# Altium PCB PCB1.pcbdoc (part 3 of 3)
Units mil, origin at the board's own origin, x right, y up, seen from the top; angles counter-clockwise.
Board outline 5971.11 x 4241.46 mil, 4 copper layers (Top Layer, Inner1, Inner2, Bottom Layer); 197 components, 112 nets, 603 pads, 396 vias.
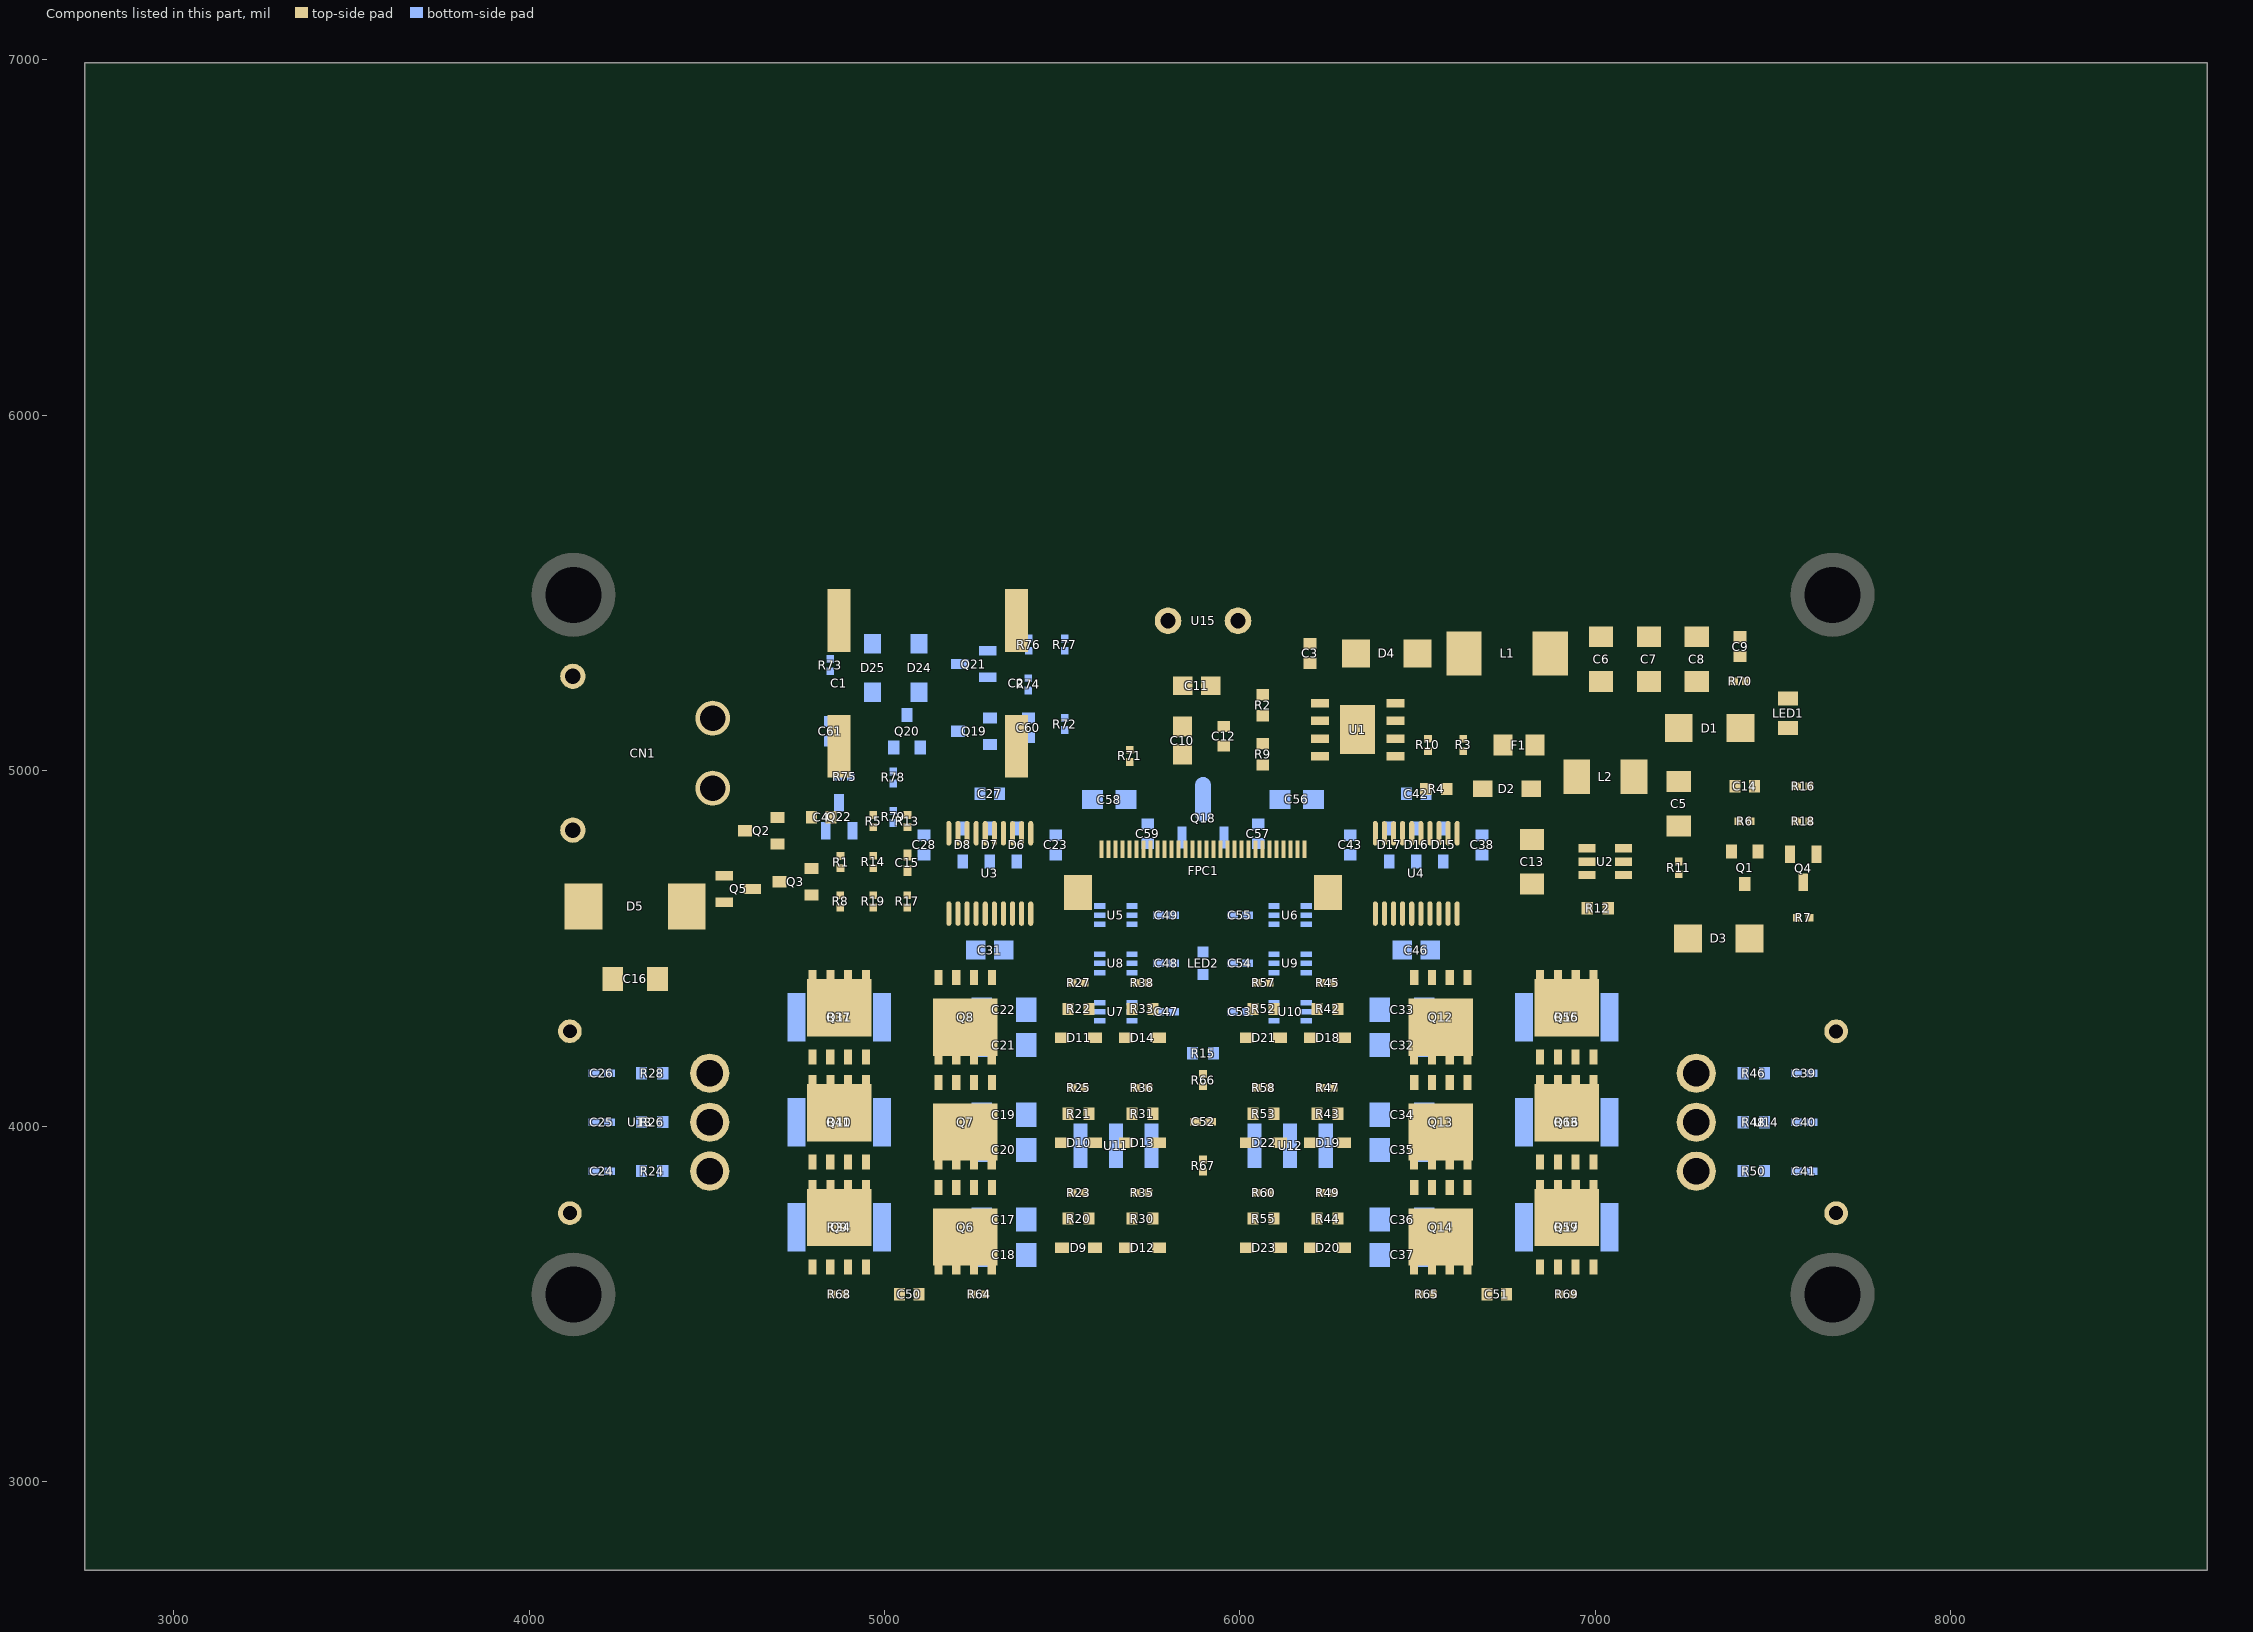
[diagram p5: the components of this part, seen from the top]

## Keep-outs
Top Layer:
  region: 6599.01,5476.96 6902.01,5476.96 6902.01,5183.96 6599.01,5183.96
  region: 6909.01,5095.96 7148.01,5095.96 7148.01,4868.67 6909.01,4868.67
Inner1:
  region: 6599.01,5476.96 6903.01,5476.96 6903.01,5183.96 6599.01,5183.96
  region: 6909.01,5095.96 7148.01,5095.96 7148.01,4868.67 6909.01,4868.67
Board Outline Layer:
  lines w10: 3999.32,3792.29 ccw(c4033.61,3759.91) 3986.54,3762.68 3986.54,3526.46 ccw(c4124.33,3526.46) 4124.33,3388.67 4360.55,3388.67 ccw(c4357.78,3435.74) 4390.16,3401.45 4426.35,3437.65 cw(c4458.73,3403.37) 4455.97,3450.44 7336,3450.44 cw(c7333.23,3403.37) 7365.61,3437.66 7401.8,3401.46 ccw(c7434.18,3435.74) 7431.42,3388.67 7667.64,3388.67 ccw(c7667.64,3526.46) 7805.43,3526.46 7805.43,3762.68 ccw(c7758.35,3759.91) 7792.64,3792.29 7756.45,3828.48 cw(c7790.73,3860.86) 7743.65,3858.1 7743.65,5163.33 cw(c7790.73,5160.56) 7756.44,5192.93 7792.64,5229.13 ccw(c7758.35,5261.51) 7805.43,5258.74 7805.43,5494.96 ccw(c7667.64,5494.96) 7667.64,5632.76 7431.42,5632.76 ccw(c7434.18,5585.68) 7401.81,5619.97 7365.61,5583.77 cw(c7333.23,5618.06) 7336,5570.98 4455.98,5570.98 ; 3999.32,5229.14 cw(c4033.61,5261.51) 3986.54,5258.74 3986.54,5494.96 cw(c4124.33,5494.96) 4124.33,5632.76 4360.55,5632.76 cw(c4357.78,5585.68) 4390.16,5619.97 4426.35,5583.77 ccw(c4458.73,5618.06) 4455.96,5570.98 ; 3999.33,3792.29 4035.52,3828.48 ; 3999.33,5229.13 4035.52,5192.94 ; 4035.53,3828.49 ccw(c4001.24,3860.86) 4048.31,3858.1 4048.31,5163.33 ccw(c4001.24,5160.56) 4035.53,5192.93

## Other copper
Top Layer:
  drawing of 460 lines, arcs and shapes, not listed
Inner1:
  region net M0_ISENSOR_PA: 4884.51,3607.82 4884.51,3599.82 4882.91,3599.6 4881.23,3599 4879.64,3598.16 4878.32,3597.19 4878.32,3610.46 4879.64,3609.49 4881.23,3608.65 4882.91,3608.05
  region net M1_ISENSOR_PC: 6857.46,3599.8 6857.46,3607.8 6859.06,3608.02 6860.74,3608.62 6862.34,3609.47 6863.65,3610.43 6863.65,3597.16 6862.34,3598.13 6860.74,3598.97 6859.06,3599.57
  region net $1N11350: 5163.83,4381.48 5163.83,4373.48 5162.23,4373.26 5160.55,4372.66 5158.96,4371.81 5157.64,4370.84 5157.64,4384.12 5158.96,4383.15 5160.55,4382.31 5162.23,4381.71
  region net $1N11350: 5503.37,4373.48 5504.15,4381.48 5505.74,4381.69 5507.41,4382.25 5509,4383.03 5510.35,4383.93 5509.57,4370.68 5508.28,4371.71 5506.69,4372.61 5504.98,4373.24
  region net M0_V: 5477.18,4113.35 5482.84,4119.01 5484.13,4118.04 5485.74,4117.27 5487.47,4116.74 5489.08,4116.49 5479.7,4107.11 5479.45,4108.72 5478.92,4110.45 5478.15,4112.06
  region net M0_U: 5477.18,3818.15 5482.84,3823.81 5484.13,3822.84 5485.74,3822.07 5487.47,3821.54 5489.08,3821.29 5479.7,3811.91 5479.45,3813.52 5478.92,3815.25 5478.15,3816.86
  region net $1N10733: 5163.83,4086.18 5163.83,4078.18 5162.23,4077.95 5160.55,4077.36 5158.96,4076.51 5157.64,4075.54 5157.64,4088.82 5158.96,4087.85 5160.55,4087.01 5162.23,4086.41
  region net $1N8638: 5163.83,3790.98 5163.83,3782.98 5162.23,3782.76 5160.55,3782.16 5158.96,3781.31 5157.64,3780.34 5157.64,3793.62 5158.96,3792.65 5160.55,3791.81 5162.23,3791.21
  region net $1N8638: 5597.11,3801.11 5591.45,3806.77 5592.42,3808.06 5593.19,3809.68 5593.72,3811.4 5593.97,3813.02 5603.35,3803.63 5601.74,3803.38 5600.01,3802.85 5598.4,3802.08
  region net M0_ISENSOR_PC: 5599.99,4391.61 5594.33,4397.27 5595.31,4398.56 5596.07,4400.18 5596.6,4401.9 5596.85,4403.52 5606.24,4394.13 5604.62,4393.88 5602.9,4393.35 5601.28,4392.58
  region net $1N11388: 5800.4,4390.91 5792.4,4390.91 5792.17,4392.51 5791.58,4394.2 5790.73,4395.79 5789.76,4397.11 5803.04,4397.11 5802.07,4395.79 5801.22,4394.2 5800.63,4392.51
  region net M0_ISENSOR_NA: 5658.79,4096.31 5653.13,4101.97 5654.1,4103.26 5654.87,4104.88 5655.4,4106.6 5655.65,4108.22 5665.04,4098.83 5663.42,4098.58 5661.7,4098.05 5660.08,4097.28
  region net $1N10771: 5787.11,4096.31 5781.45,4101.97 5782.42,4103.26 5783.19,4104.88 5783.72,4106.6 5783.97,4108.22 5793.35,4098.83 5791.74,4098.58 5790.01,4098.05 5788.4,4097.28
  region net $1N11388: 5119.33,4171.71 5119.33,4163.71 5117.73,4163.49 5116.05,4162.89 5114.46,4162.04 5113.14,4161.08 5113.14,4174.35 5114.46,4173.38 5116.05,4172.54 5117.73,4171.94
  region net $1N10771: 5119.33,3876.46 5119.33,3868.46 5117.73,3868.23 5116.05,3867.63 5114.46,3866.79 5113.14,3865.82 5113.14,3879.1 5114.46,3878.13 5116.05,3877.28 5117.73,3876.68
  region net M1_ISENSOR_NA: 6138.83,4101.97 6133.17,4096.31 6131.88,4097.28 6130.27,4098.05 6128.54,4098.58 6126.93,4098.83 6136.31,4108.22 6136.56,4106.6 6137.09,4104.88 6137.86,4103.26
  region net $1N20194: 6478.35,4373.46 6478.32,4381.46 6479.92,4381.69 6481.61,4382.29 6483.2,4383.14 6484.52,4384.11 6484.54,4370.83 6483.22,4371.8 6481.63,4372.64 6479.95,4373.24
  region net $1N20187: 6478.34,4078.16 6478.33,4086.16 6479.93,4086.39 6481.62,4086.99 6483.21,4087.83 6484.53,4088.8 6484.53,4075.53 6483.21,4076.49 6481.62,4077.34 6479.94,4077.94
  region net $1N20219: 6466.21,3782.98 6466.21,3790.98 6467.81,3791.21 6469.5,3791.81 6471.09,3792.65 6472.41,3793.62 6472.41,3780.34 6471.09,3781.31 6469.5,3782.16 6467.81,3782.76
  region net $1N20159: 6672.63,3859.64 6672.63,3867.64 6674.23,3867.87 6675.92,3868.46 6677.51,3869.31 6678.83,3870.28 6678.83,3857 6677.51,3857.97 6675.92,3858.81 6674.23,3859.41
  region net M1_ISENSOR_PC: 6094.66,3872.78 6089.18,3866.94 6087.89,3867.91 6086.26,3868.68 6084.52,3869.19 6082.9,3869.42 6092.1,3878.99 6092.37,3877.38 6092.91,3875.67 6093.69,3874.07
  region net $1N20164: 6060.58,4362.17 6054.92,4356.51 6053.63,4357.48 6052.02,4358.25 6050.3,4358.78 6048.68,4359.03 6058.07,4368.42 6058.31,4366.8 6058.84,4365.08 6059.61,4363.46
  region net M1_U: 6320.17,4406.96 6320.17,4398.96 6318.57,4398.74 6316.89,4398.14 6315.3,4397.29 6313.98,4396.33 6313.98,4409.6 6315.3,4408.63 6316.89,4407.79 6318.57,4407.19
  region net $1N20194: 6305.9,4381.46 6305.9,4373.46 6304.3,4373.24 6302.62,4372.64 6301.02,4371.79 6299.71,4370.83 6299.71,4384.1 6301.02,4383.13 6302.62,4382.29 6304.3,4381.69
  region net M1_W: 6308.81,3823.81 6314.47,3818.15 6313.5,3816.86 6312.73,3815.25 6312.2,3813.52 6311.96,3811.91 6302.57,3821.29 6304.19,3821.54 6305.91,3822.07 6307.52,3822.84
  region net M1_V: 6309.11,4119.01 6314.77,4113.35 6313.8,4112.06 6313.03,4110.45 6312.5,4108.72 6312.25,4107.11 6302.86,4116.49 6304.48,4116.74 6306.2,4117.27 6307.82,4118.04
  region net M1_LC: 6124.69,3745.18 6130.35,3750.84 6131.64,3749.87 6133.25,3749.1 6134.98,3748.57 6136.59,3748.32 6127.21,3738.94 6126.96,3740.55 6126.43,3742.28 6125.66,3743.89
  region net M1_LB: 6124.69,4040.38 6130.35,4046.04 6131.64,4045.07 6133.25,4044.3 6134.98,4043.77 6136.59,4043.52 6127.21,4034.14 6126.96,4035.75 6126.43,4037.48 6125.66,4039.09
  region net M1_LC: 6346.63,4569.85 6352.29,4575.51 6353.58,4574.54 6355.2,4573.77 6356.92,4573.24 6358.54,4573 6349.15,4563.61 6348.9,4565.23 6348.37,4566.95 6347.6,4568.56
  region net M1_LB: 6333.63,4547.65 6339.29,4553.31 6340.58,4552.34 6342.2,4551.57 6343.92,4551.04 6345.54,4550.8 6336.15,4541.41 6335.9,4543.03 6335.37,4544.75 6334.6,4546.36
  region net M1_W: 6596.93,4701.67 6591.27,4696.01 6589.98,4696.98 6588.37,4697.75 6586.64,4698.28 6585.03,4698.53 6594.41,4707.92 6594.66,4706.3 6595.19,4704.58 6595.96,4702.96
  region net M1_U: 6444.08,4711.36 6444.08,4703.36 6442.48,4703.14 6440.8,4702.54 6439.2,4701.69 6437.88,4700.73 6437.88,4714 6439.2,4713.03 6440.8,4712.19 6442.48,4711.59
  region net M0_U: 5236.03,4695.31 5228.03,4695.31 5227.8,4696.91 5227.21,4698.6 5226.36,4700.19 5225.39,4701.51 5238.67,4701.51 5237.7,4700.19 5236.86,4698.6 5236.26,4696.91
  region net M0_W: 5389.58,4695.31 5381.58,4695.31 5381.35,4696.91 5380.76,4698.6 5379.91,4700.19 5378.94,4701.51 5392.22,4701.51 5391.25,4700.19 5390.41,4698.6 5389.81,4696.91
  region net $1N20164: 6552.79,4154.91 6552.79,4162.91 6554.39,4163.14 6556.08,4163.74 6557.67,4164.58 6558.99,4165.55 6558.99,4152.28 6557.67,4153.25 6556.08,4154.09 6554.39,4154.69
  region net M1_ISENSOR_PA: 6672.65,4190.35 6672.65,4198.35 6674.25,4198.57 6675.93,4199.17 6677.52,4200.02 6678.84,4200.99 6678.84,4187.71 6677.52,4188.68 6675.93,4189.52 6674.25,4190.12
  region net M1_ISENSOR_NA: 6672.63,3895.07 6672.63,3903.07 6674.23,3903.3 6675.92,3903.9 6677.51,3904.74 6678.83,3905.71 6678.83,3892.43 6677.51,3893.4 6675.92,3894.25 6674.23,3894.85
  region net M0_ISENSOR_PC: 5119.33,4198.32 5119.33,4190.32 5117.73,4190.1 5116.05,4189.5 5114.46,4188.65 5113.14,4187.69 5113.14,4200.96 5114.46,4199.99 5116.05,4199.15 5117.73,4198.55
  region net M0_ISENSOR_NA: 5119.33,3903.07 5119.33,3895.07 5117.73,3894.84 5116.05,3894.24 5114.46,3893.4 5113.14,3892.43 5113.14,3905.71 5114.46,3904.74 5116.05,3903.89 5117.73,3903.3
  region net M0_BK_OUT: 5446.98,5360.18 5438.98,5360.18 5438.76,5361.78 5438.16,5363.47 5437.31,5365.06 5436.35,5366.38 5449.62,5366.38 5448.65,5365.06 5447.81,5363.47 5447.21,5361.78
  region net M1_BK_OUT: 5481.03,5001.96 5481.03,4993.96 5479.43,4993.74 5477.75,4993.14 5476.16,4992.29 5474.84,4991.33 5474.84,5004.6 5476.16,5003.63 5477.75,5002.79 5479.43,5002.19
  region net M0_V: 5312.81,4864.61 5304.81,4864.61 5304.58,4866.21 5303.99,4867.9 5303.14,4869.49 5302.17,4870.81 5315.45,4870.81 5314.48,4869.49 5313.64,4867.9 5313.04,4866.21
  region net M1_V: 6512.81,4865.76 6504.81,4865.75 6504.58,4867.35 6503.99,4869.04 6503.14,4870.63 6502.17,4871.95 6515.45,4871.95 6514.48,4870.63 6513.63,4869.04 6513.04,4867.36
  region net M0_ADC_A: 5849.93,4725.31 5841.93,4726.57 5841.74,4728.15 5841.21,4729.81 5840.46,4731.4 5839.61,4732.77 5852.83,4731.51 5851.76,4730.24 5850.84,4728.64 5850.18,4726.92
  region net M1_TIM8_CH3N: 6461.62,4633.43 6453.62,4633.43 6453.39,4634.91 6452.79,4636.35 6451.95,4637.69 6450.98,4638.89 6464.25,4638.89 6463.29,4637.69 6462.44,4636.35 6461.84,4634.91
  region net M1_TIM8_CH1: 6419.98,4640.74 6419.98,4648.74 6421.58,4648.97 6423.26,4649.57 6424.85,4650.41 6426.17,4651.38 6426.17,4638.11 6424.85,4639.07 6423.26,4639.92 6421.58,4640.52
  region net M1_TIM8_CH3N: 6136.35,4845.77 6130.7,4851.43 6131.67,4852.72 6132.44,4854.33 6132.96,4856.05 6133.21,4857.67 6142.6,4848.28 6140.98,4848.04 6139.26,4847.51 6137.64,4846.74
  region net M1_TIM8_CH1: 6153.39,4811.14 6147.74,4805.48 6146.45,4806.45 6144.83,4807.22 6143.11,4807.75 6141.49,4808 6150.88,4817.38 6151.12,4815.77 6151.65,4814.04 6152.42,4812.43
  region net M0_ADC_A: 5639.67,4630.69 5645.33,4625.03 5644.36,4623.74 5643.59,4622.13 5643.06,4620.41 5642.82,4618.79 5633.43,4628.18 5635.05,4628.42 5636.77,4628.95 5638.38,4629.72
  region net M0_ADC_C: 5627.68,4528.37 5635.68,4528.37 5635.91,4526.77 5636.51,4525.09 5637.35,4523.5 5638.32,4522.18 5625.05,4522.18 5626.01,4523.5 5626.86,4525.09 5627.46,4526.77
  region net M0_ADC: 5988.56,4706.91 5980.56,4706.91 5980.34,4708.51 5979.74,4710.2 5978.9,4711.79 5977.93,4713.11 5991.2,4713.11 5990.23,4711.79 5989.39,4710.2 5988.79,4708.51
  region net VOLTAGE_ADC: 5874.8,4743.65 5880.45,4749.31 5881.74,4748.34 5883.36,4747.57 5885.08,4747.04 5886.7,4746.8 5877.31,4737.41 5877.06,4739.03 5876.54,4740.75 5875.77,4742.36
  region net M0_ADC: 5645.58,4373.86 5645.58,4365.86 5643.98,4365.64 5642.29,4365.04 5640.7,4364.19 5639.38,4363.23 5639.38,4376.5 5640.7,4375.53 5642.29,4374.69 5643.98,4374.09
  region net M1_ISENSOR_PA: 6257.98,4420.75 6249.98,4420.75 6249.76,4422.35 6249.16,4424.04 6248.31,4425.63 6247.35,4426.95 6260.62,4426.95 6259.65,4425.63 6258.81,4424.04 6258.21,4422.35
  region net +5V: 7417.78,5048.56 7397.78,5048.56 7397.7,5051.21 7397.47,5053.71 7396.78,5058.09 7396.1,5061.3 7395.78,5062.96 7419.78,5062.96 7419.47,5061.3 7418.78,5058.09 7418.1,5053.71 7417.87,5051.21
  region net M1_BK_OUT: 5696.93,4818.63 5696.93,4826.63 5698.52,4826.86 5700.21,4827.45 5701.8,4828.3 5703.12,4829.27 5703.12,4815.99 5701.8,4816.96 5700.21,4817.81 5698.52,4818.4
  region net M0_BK_OUT: 5686.73,4870.22 5694.73,4868.05 5694.91,4866.49 5695.37,4864.84 5696.03,4863.24 5696.79,4861.85 5683.69,4864.02 5684.81,4865.24 5685.78,4866.85 5686.47,4868.6
  region net M0_BK_OUT: 5677.93,4862.85 5683.59,4868.51 5684.88,4867.54 5686.5,4866.77 5688.22,4866.24 5689.84,4866 5680.45,4856.61 5680.2,4858.23 5679.67,4859.95 5678.9,4861.56
  region net $1N126462: 4921.46,4872.96 4921.46,4864.96 4919.86,4864.74 4918.17,4864.14 4916.58,4863.29 4915.26,4862.33 4915.26,4875.6 4916.58,4874.63 4918.17,4873.79 4919.86,4873.19
  region net $1N126462: 5012.66,4828.68 5018.32,4834.34 5019.61,4833.36 5021.22,4832.6 5022.94,4832.07 5024.56,4831.82 5015.17,4822.43 5014.93,4824.05 5014.4,4825.77 5013.63,4827.39
  region net $1N126467: 4876.48,4966.11 4882.13,4960.46 4881.16,4959.17 4880.39,4957.55 4879.87,4955.83 4879.62,4954.21 4870.23,4963.6 4871.85,4963.85 4873.57,4964.37 4875.19,4965.14
  region net $1N126467: 4951.98,5126.91 4943.98,5126.91 4943.76,5128.51 4943.16,5130.2 4942.31,5131.79 4941.35,5133.11 4954.62,5133.11 4953.65,5131.79 4952.81,5130.2 4952.21,5128.51
  region net $1N168458: 6188.03,5044.34 6188.03,5036.34 6186.43,5036.11 6184.75,5035.51 6183.16,5034.67 6181.84,5033.7 6181.84,5046.97 6183.16,5046 6184.75,5045.16 6186.43,5044.56
  region net $1N168458: 6494.15,5044.47 6487.8,5049.44 6488.77,5050.75 6489.52,5052.41 6490.01,5054.19 6490.17,5055.83 6500.23,5047.16 6498.64,5046.82 6496.98,5046.24 6495.41,5045.45
  region net $1N20159: 6315.17,3867.64 6315.17,3859.64 6313.57,3859.41 6311.89,3858.81 6310.3,3857.97 6308.98,3857 6308.98,3870.28 6310.3,3869.31 6311.89,3868.46 6313.57,3867.87
  region net VOLTAGE_ADC: 5070.11,4823.17 5075.77,4817.52 5074.8,4816.22 5074.03,4814.61 5073.5,4812.89 5073.25,4811.27 5063.87,4820.66 5065.48,4820.9 5067.21,4821.43 5068.82,4822.2
  region net M0_ISENSOR_PA: 5702.89,3767.71 5697.23,3773.37 5698.2,3774.66 5698.97,3776.28 5699.5,3778 5699.75,3779.62 5709.14,3770.23 5707.52,3769.98 5705.8,3769.45 5704.18,3768.68
  region net M0_W: 5289.04,4421.54 5289.04,4413.54 5287.44,4413.31 5285.75,4412.71 5284.16,4411.87 5282.84,4410.9 5282.84,4424.18 5284.16,4423.21 5285.75,4422.36 5287.44,4421.77
  region net M0_W: 5272.99,4429.59 5280.99,4429.59 5281.22,4427.99 5281.81,4426.3 5282.66,4424.71 5283.63,4423.39 5270.35,4423.39 5271.32,4424.71 5272.16,4426.3 5272.76,4427.99
  region net M0_V: 5214.7,4118.22 5214.75,4126.22 5216.35,4126.45 5218.04,4127.04 5219.63,4127.88 5220.95,4128.85 5220.89,4115.57 5219.57,4116.55 5217.98,4117.4 5216.3,4118
  region net M0_U: 5214.74,3821.09 5214.74,3829.09 5216.34,3829.31 5218.02,3829.91 5219.62,3830.75 5220.94,3831.72 5220.94,3818.45 5219.62,3819.42 5218.02,3820.26 5216.34,3820.86
  region net M1_W: 6627.62,3831.02 6627.62,3823.02 6626.02,3822.8 6624.34,3822.2 6622.74,3821.36 6621.42,3820.39 6621.42,3833.66 6622.74,3832.69 6624.34,3831.85 6626.02,3831.25
  region net M1_V: 6553.32,4118.22 6553.32,4126.22 6554.92,4126.45 6556.61,4127.05 6558.2,4127.89 6559.52,4128.86 6559.52,4115.59 6558.2,4116.56 6556.61,4117.4 6554.92,4118
  region net M1_V: 6627.62,4126.22 6627.62,4118.22 6626.02,4118 6624.34,4117.4 6622.74,4116.56 6621.42,4115.59 6621.42,4128.86 6622.74,4127.89 6624.34,4127.05 6626.02,4126.45
  region net M1_U: 6559.68,4406.18 6554.02,4411.83 6554.99,4413.12 6555.76,4414.74 6556.29,4416.46 6556.54,4418.08 6565.93,4408.69 6564.31,4408.44 6562.59,4407.92 6560.97,4407.15
  region net M1_U: 6561.37,4429.57 6569.37,4429.57 6569.6,4427.97 6570.2,4426.29 6571.04,4424.7 6572.01,4423.38 6558.73,4423.38 6559.7,4424.7 6560.55,4426.29 6561.15,4427.97
  region net M0_W: 5466.47,4409.3 5472.13,4414.96 5473.42,4413.99 5475.03,4413.22 5476.76,4412.69 5478.37,4412.44 5468.99,4403.06 5468.74,4404.67 5468.21,4406.4 5467.44,4408.01
  region net M1_ISENSOR_PC: 6182.28,4389.68 6190.28,4389.68 6190.51,4388.08 6191.11,4386.4 6191.95,4384.8 6192.92,4383.49 6179.65,4383.49 6180.61,4384.8 6181.46,4386.4 6182.06,4388.08
  region net M1_ISENSOR_PC: 6190.28,4526.4 6182.28,4526.4 6182.06,4528 6181.46,4529.68 6180.61,4531.27 6179.65,4532.59 6192.92,4532.59 6191.95,4531.27 6191.11,4529.68 6190.51,4528
  region net $1N20187: 6228.63,4086.16 6228.63,4078.16 6227.03,4077.94 6225.35,4077.34 6223.76,4076.49 6222.44,4075.53 6222.44,4088.8 6223.76,4087.83 6225.35,4086.99 6227.03,4086.39
  region net $1N20219: 6200.2,3806.77 6194.54,3801.11 6193.25,3802.08 6191.64,3802.85 6189.92,3803.38 6188.3,3803.63 6197.69,3813.02 6197.93,3811.4 6198.46,3809.68 6199.23,3808.06
  region net PVCC: 4888.06,4790.96 4888.06,4782.96 4886.46,4782.74 4884.77,4782.14 4883.18,4781.29 4881.86,4780.33 4881.86,4793.6 4883.18,4792.63 4884.77,4791.79 4886.46,4791.19
  region net PVCC: 4919.93,4782.96 4919.93,4790.96 4921.53,4791.19 4923.22,4791.79 4924.81,4792.63 4926.13,4793.6 4926.13,4780.33 4924.81,4781.29 4923.22,4782.14 4921.53,4782.74
  region net +5V: 5951.98,3824.04 5931.98,3824.04 5932.21,3827.12 5932.48,3829.72 5932.45,3830.92 5932.2,3832.1 5931.65,3833.3 5930.73,3834.54 5953.23,3834.54 5952.32,3833.3 5951.77,3832.1 5951.52,3830.92 5951.48,3829.72 5951.76,3827.12
Inner2:
  region net M0_ISENSOR_PC: 4884.51,4198.32 4884.51,4190.32 4882.91,4190.1 4881.23,4189.5 4879.64,4188.65 4878.32,4187.69 4878.32,4200.96 4879.64,4199.99 4881.23,4199.15 4882.91,4198.55
  region net M0_ISENSOR_NA: 4884.51,3903.07 4884.51,3895.07 4882.91,3894.84 4881.23,3894.24 4879.64,3893.4 4878.32,3892.43 4878.32,3905.71 4879.64,3904.74 4881.23,3903.89 4882.91,3903.3
  region net $1N9358: 5786.8,3800.41 5778.8,3800.41 5778.57,3802.01 5777.98,3803.7 5777.13,3805.29 5776.16,3806.61 5789.44,3806.61 5788.47,3805.29 5787.62,3803.7 5787.03,3802.01
  region net $1N9358: 4959.33,3566.21 4959.33,3558.21 4957.73,3557.99 4956.05,3557.39 4954.46,3556.54 4953.14,3555.58 4953.14,3568.85 4954.46,3567.88 4956.05,3567.04 4957.73,3566.44
  region net $1N20215: 6982.43,3564.36 6982.43,3572.36 6984.03,3572.59 6985.72,3573.19 6987.31,3574.03 6988.63,3575 6988.63,3561.73 6987.31,3562.69 6985.72,3563.54 6984.03,3564.14
  region net $1N20164: 6748.66,4154.91 6748.66,4162.91 6750.26,4163.14 6751.94,4163.74 6753.54,4164.58 6754.85,4165.55 6754.85,4152.28 6753.54,4153.25 6751.94,4154.09 6750.26,4154.69
  region net M0_HA: 5464.56,3745.18 5470.22,3750.84 5471.51,3749.87 5473.12,3749.1 5474.85,3748.57 5476.46,3748.32 5467.08,3738.94 5466.83,3740.55 5466.3,3742.28 5465.53,3743.89
  region net M0_LA: 5422.52,4872.11 5416.86,4866.46 5415.57,4867.43 5413.95,4868.2 5412.23,4868.72 5410.61,4868.97 5420,4878.36 5420.25,4876.74 5420.78,4875.02 5421.54,4873.4
  region net M0_HB: 5464.56,4040.38 5470.22,4046.04 5471.51,4045.07 5473.12,4044.3 5474.85,4043.77 5476.46,4043.52 5467.08,4034.14 5466.83,4035.75 5466.3,4037.48 5465.53,4039.09
  region net M0_HC: 5449.56,4335.68 5455.22,4341.34 5456.51,4340.37 5458.12,4339.6 5459.85,4339.07 5461.46,4338.82 5452.08,4329.44 5451.83,4331.05 5451.3,4332.78 5450.53,4334.39
  region net M0_HC: 5363.98,4695.31 5355.98,4695.31 5355.76,4696.91 5355.16,4698.6 5354.31,4700.19 5353.35,4701.51 5366.62,4701.51 5365.65,4700.19 5364.81,4698.6 5364.21,4696.91
  region net M0_LC: 5396.93,4537.4 5391.27,4531.75 5389.98,4532.72 5388.36,4533.49 5386.64,4534.01 5385.02,4534.26 5394.41,4543.65 5394.66,4542.03 5395.19,4540.31 5395.95,4538.69
  region net M0_LB: 5423.22,4558.09 5423.22,4550.09 5421.62,4549.87 5419.93,4549.27 5418.34,4548.42 5417.02,4547.46 5417.02,4560.73 5418.34,4559.76 5419.93,4558.92 5421.62,4558.32
  region net M0_LB: 5657.69,4046.32 5666.49,4043.82 5665.43,4042.41 5664.65,4040.68 5664.27,4038.85 5664.27,4037.96 5664.42,4037.13 5652.43,4042.83 5655.19,4044.38 5656.58,4045.37
  region net M0_LC: 5626.86,4325.99 5626.86,4333.99 5628.46,4334.22 5630.15,4334.82 5631.74,4335.66 5633.06,4336.63 5633.06,4323.35 5631.74,4324.32 5630.15,4325.17 5628.46,4325.77
  region net M0_LA: 5668.91,3791.11 5676.91,3791.11 5677.14,3789.51 5677.73,3787.83 5678.58,3786.24 5679.55,3784.92 5666.27,3784.92 5667.24,3786.24 5668.09,3787.83 5668.68,3789.51
  region net $1N20215: 6020.2,3806.77 6014.54,3801.11 6013.25,3802.08 6011.64,3802.85 6009.92,3803.38 6008.3,3803.63 6017.69,3813.02 6017.93,3811.4 6018.46,3809.68 6019.23,3808.06
  region net M1_HA: 6315.57,4341.31 6321.22,4335.65 6320.25,4334.36 6319.48,4332.75 6318.95,4331.03 6318.71,4329.41 6309.32,4338.8 6310.94,4339.04 6312.66,4339.57 6314.27,4340.34
  region net M1_HB: 6321.73,4046.04 6327.39,4040.38 6326.42,4039.09 6325.65,4037.48 6325.12,4035.75 6324.87,4034.14 6315.48,4043.52 6317.1,4043.77 6318.82,4044.3 6320.44,4045.07
  region net M1_HC: 6321.73,3750.84 6327.39,3745.18 6326.42,3743.89 6325.65,3742.28 6325.12,3740.55 6324.87,3738.94 6315.48,3748.32 6317.1,3748.57 6318.82,3749.1 6320.44,3749.87
  region net M1_HB: 6487.22,4695.31 6479.22,4695.31 6478.99,4696.91 6478.4,4698.6 6477.55,4700.19 6476.58,4701.51 6489.86,4701.51 6488.89,4700.19 6488.05,4698.6 6487.45,4696.91
  region net M1_HA: 6410.44,4695.31 6402.44,4695.31 6402.21,4696.91 6401.61,4698.6 6400.77,4700.19 6399.8,4701.51 6413.07,4701.51 6412.11,4700.19 6411.26,4698.6 6410.66,4696.91
  region net $1N20164: 6576.89,4162.91 6576.89,4154.91 6575.29,4154.69 6573.6,4154.09 6572.01,4153.25 6570.69,4152.28 6570.69,4165.55 6572.01,4164.58 6573.6,4163.74 6575.29,4163.14
  region net M0_ISENSOR_PC: 5095.23,4190.32 5095.23,4198.32 5096.83,4198.55 5098.52,4199.15 5100.11,4199.99 5101.43,4200.96 5101.43,4187.69 5100.11,4188.65 5098.52,4189.5 5096.83,4190.1
  region net M0_ISENSOR_NA: 5095.23,3895.07 5095.23,3903.07 5096.83,3903.3 5098.52,3903.89 5100.11,3904.74 5101.43,3905.71 5101.43,3892.43 5100.11,3893.4 5098.52,3894.24 5096.83,3894.84
  region net M0_HB: 5287.21,4695.31 5279.21,4695.31 5278.99,4696.91 5278.39,4698.6 5277.54,4700.19 5276.57,4701.51 5289.85,4701.51 5288.88,4700.19 5288.04,4698.6 5287.44,4696.91
  region net M1_LA: 6599.11,4765.63 6599.11,4773.63 6600.71,4773.86 6602.4,4774.46 6603.99,4775.3 6605.31,4776.27 6605.31,4762.99 6603.99,4763.96 6602.4,4764.81 6600.71,4765.41
  region net M0_HA: 5210.44,4695.31 5202.44,4695.31 5202.21,4696.91 5201.61,4698.6 5200.77,4700.19 5199.8,4701.51 5213.07,4701.51 5212.11,4700.19 5211.26,4698.6 5210.66,4696.91
  region net M1_HC: 6554.3,4690.01 6548.64,4695.67 6549.61,4696.96 6550.38,4698.58 6550.91,4700.3 6551.15,4701.92 6560.54,4692.53 6558.92,4692.28 6557.2,4691.75 6555.59,4690.98
  region net MOTOR_EN1: 6805.03,4523.56 6805.03,4515.56 6803.43,4515.34 6801.75,4514.74 6800.16,4513.89 6798.84,4512.93 6798.84,4526.2 6800.16,4525.23 6801.75,4524.39 6803.43,4523.79
  region net MOTOR_EN1: 7541.29,4944.61 7535.63,4950.27 7536.6,4951.56 7537.37,4953.18 7537.9,4954.9 7538.15,4956.52 7547.54,4947.13 7545.92,4946.88 7544.2,4946.35 7542.58,4945.59
  region net TEMP1_ADC: 5929.51,4725.91 5921.51,4725.91 5921.29,4727.51 5920.69,4729.2 5919.85,4730.79 5918.88,4732.11 5932.15,4732.11 5931.18,4730.79 5930.34,4729.2 5929.74,4727.51
  region net S1_PWM: 5968.88,4725.91 5960.88,4725.91 5960.66,4727.51 5960.06,4729.2 5959.22,4730.79 5958.25,4732.11 5971.52,4732.11 5970.55,4730.79 5969.71,4729.2 5969.11,4727.51
  region net M1_ADC: 6008.25,4725.91 6000.25,4725.91 6000.03,4727.51 5999.43,4729.2 5998.59,4730.79 5997.62,4732.11 6010.89,4732.11 6009.92,4730.79 6009.08,4729.2 6008.48,4727.51
  region net M1_ADC_C: 6047.62,4725.91 6039.62,4725.91 6039.4,4727.51 6038.8,4729.2 6037.96,4730.79 6036.99,4732.11 6050.26,4732.11 6049.29,4730.79 6048.45,4729.2 6047.85,4727.51
  region net M1_ADC_C: 6137.63,4436.65 6143.29,4442.31 6144.58,4441.34 6146.2,4440.57 6147.92,4440.04 6149.54,4439.8 6140.15,4430.41 6139.9,4432.03 6139.37,4433.75 6138.6,4435.36
  region net M1_ADC: 6149.99,4291.91 6149.99,4299.91 6151.59,4300.13 6153.27,4300.73 6154.87,4301.58 6156.18,4302.54 6156.18,4289.27 6154.87,4290.24 6153.27,4291.08 6151.59,4291.68
  region net S1_PWM: 6181.93,3987.96 6181.93,3995.96 6183.53,3996.19 6185.22,3996.79 6186.81,3997.63 6188.13,3998.6 6188.13,3985.33 6186.81,3986.29 6185.22,3987.14 6183.53,3987.74
  region net S0_PWM: 5846.49,3850.06 5852.15,3844.4 5851.18,3843.11 5850.41,3841.5 5849.88,3839.78 5849.63,3838.16 5840.25,3847.54 5841.86,3847.79 5843.59,3848.32 5845.2,3849.09
  region net TEMP0_ADC: 5788.49,3876.31 5794.15,3870.65 5793.18,3869.36 5792.41,3867.75 5791.88,3866.03 5791.63,3864.41 5782.25,3873.8 5783.86,3874.04 5785.59,3874.57 5787.2,3875.34
  region net M1_ISENSOR_PC: 6088.97,4190.75 6094.63,4185.09 6093.66,4183.8 6092.89,4182.18 6092.36,4180.46 6092.12,4178.84 6082.73,4188.23 6084.35,4188.48 6086.07,4189.01 6087.68,4189.78
  region net M1_LA: 6101.63,4381.44 6107.29,4375.78 6106.32,4374.49 6105.55,4372.87 6105.02,4371.15 6104.78,4369.53 6095.39,4378.92 6097.01,4379.17 6098.73,4379.7 6100.34,4380.47
  region net $1N36459: 5864.29,4530.61 5858.63,4536.27 5859.6,4537.56 5860.37,4539.18 5860.9,4540.9 5861.15,4542.52 5870.54,4533.13 5868.92,4532.88 5867.2,4532.35 5865.58,4531.59
  region net $1N36459: 5677.96,4989.96 5677.96,4997.96 5679.56,4998.19 5681.24,4998.79 5682.83,4999.63 5684.15,5000.6 5684.15,4987.33 5682.83,4988.29 5681.24,4989.14 5679.56,4989.74
  region net DGND: 5053.74,3510.21 5053.74,3502.21 5052.14,3501.98 5050.46,3501.39 5048.87,3500.54 5047.55,3499.57 5047.55,3512.85 5048.87,3511.88 5050.46,3511.03 5052.14,3510.44
  region net DGND: 6738.22,3502.21 6738.22,3510.21 6739.82,3510.44 6741.51,3511.03 6743.1,3511.88 6744.42,3512.85 6744.42,3499.57 6743.1,3500.54 6741.51,3501.39 6739.82,3501.98
  region net DGND: 5890.29,3836.31 5884.63,3841.97 5885.6,3843.26 5886.37,3844.88 5886.9,3846.6 5887.15,3848.22 5896.54,3838.83 5894.92,3838.58 5893.2,3838.05 5891.58,3837.28
  region net DGND: 5907.33,3841.97 5901.67,3836.31 5900.38,3837.28 5898.77,3838.05 5897.05,3838.58 5895.43,3838.83 5904.82,3848.22 5905.06,3846.6 5905.59,3844.88 5906.36,3843.26
  region net $1N20159: 6299.12,3875.69 6307.12,3875.69 6307.35,3874.09 6307.95,3872.4 6308.79,3870.81 6309.76,3869.49 6296.49,3869.49 6297.45,3870.81 6298.3,3872.4 6298.9,3874.09
  region net +3.3V: 5732.51,4560.64 5732.51,4575.64 5736.27,4575.85 5739.44,4576.32 5743.13,4576.99 5743.13,4559.29 5739.44,4559.97 5736.27,4560.43
  region net +3.3V: 5731.34,5048.38 5716.34,5048.38 5716.13,5052.14 5715.67,5055.31 5714.99,5059 5732.69,5059 5732.02,5055.31 5731.55,5052.14
  region net M0_ISENSOR_PA: 5617.73,4545.56 5617.73,4537.56 5616.13,4537.34 5614.45,4536.74 5612.86,4535.89 5611.54,4534.93 5611.54,4548.2 5612.86,4547.23 5614.45,4546.39 5616.13,4545.79
  region net M0_ISENSOR_PA: 5714.27,3790.41 5719.93,3784.75 5718.96,3783.46 5718.19,3781.85 5717.66,3780.13 5717.42,3778.51 5708.03,3787.9 5709.65,3788.14 5711.37,3788.67 5712.98,3789.44
  region net $1N20159: 6060.59,4069.57 6054.93,4063.91 6053.64,4064.89 6052.03,4065.65 6050.31,4066.18 6048.69,4066.43 6058.08,4075.82 6058.32,4074.2 6058.85,4072.48 6059.62,4070.86
  region net PGND: 5873.82,4227.09 5858.82,4227.09 5858.9,4229.46 5858.9,4231.6 5858.77,4232.61 5858.49,4233.58 5858.02,4234.54 5857.32,4235.49 5875.32,4235.49 5874.62,4234.54 5874.15,4233.58 5873.87,4232.61 5873.74,4231.6 5873.75,4229.46
  region net PGND: 5844.03,3981.32 5854.64,3970.71 5852.91,3969.09 5851.39,3967.58 5850.77,3966.77 5850.28,3965.88 5849.93,3964.87 5849.76,3963.71 5837.03,3976.44 5838.19,3976.61 5839.2,3976.96 5840.09,3977.45 5840.9,3978.07 5842.41,3979.59
  region net M1_ISENSOR_PC: 6190.28,4365.58 6182.28,4365.58 6182.06,4367.18 6181.46,4368.87 6180.61,4370.46 6179.65,4371.78 6192.92,4371.78 6191.95,4370.46 6191.11,4368.87 6190.51,4367.18
Bottom Layer:
  drawing of 272 lines, arcs and shapes, not listed

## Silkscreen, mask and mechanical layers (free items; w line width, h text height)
Top Silkscreen Layer:
  drawing of 111 lines, arcs and shapes, not listed
  text "5V_LED" at 7458.76,5258.42 h50
  text "Motor_Ctrl" at 5687.27,4852.87 h80
  text "JLCJLCJLCJLC" at 5746.01,4643.86 h39.37
  text "SVPWM" at 4326.91,3504.92 h70
  text "SVPWM" at 7192.43,3504.92 h70
Bottom Silkscreen Layer:
  drawing of 259 lines, arcs and shapes, not listed
  text "~" at 4498.01,5319.86 h60 r180
  text "24" at 4460.08,5258.63 h50
  text "12" at 4633.79,5258.48 h50
  text "-" at 4653.19,5150.18 h100 r180
  text "MOTORS DRIVER" at 7118.01,5095.96 h90
  text "FOC" at 7432.26,5083.91 h100
  text "+" at 4645.35,5048.35 h78.74 r180
  text "Voltage/Current Measurement" at 7437.34,4994.07 h60
  text "[Dual Brushless Motors]" at 7437.34,4921.9 h60
  text "[Dual Servo Motors]" at 7437.34,4856.14 h60
  text "Current Loop" at 7437.34,4790.37 h60
  text "30" at 4485.57,4730.65 h50
  text "PW-M" at 4415.7,4727.25 h50
  text "XT" at 4563.79,4727.1 h50
  text "Brake" at 7437.34,4718.21 h60
  text "NTC" at 7437.34,4652.45 h60
  text "BRAKE" at 4955.01,4627.96 h50
  text "30" at 4478.11,4574.28 h50
  text "PW-M" at 4409.74,4570.87 h50
  text "MR" at 4573.79,4570.58 h50
  text "MOTOR0" at 4663.08,4338.96 h100
  text "MOTOR1" at 7621.03,4338.96 h100
  text "30" at 8377.8,4251.28 h50
  text "MR" at 8467.34,4248.58 h50
  text "PW-M" at 8309.93,4247.87 h50
  text "▲" at 8275.07,4231.91 h70 r180
  text "PWM" at 5700.49,4175.33 h50
  text "PWM" at 6191.14,4175.33 h50
  text "▲" at 8280.21,4172.93 h60 r180
  text "▲" at 8280.21,4122.73 h60 r180
  text "5V" at 5627.98,4103.37 h50
  text "5V" at 6222.97,4103.37 h50
  text "S0" at 5739.63,4097.41 h50
  text "S1" at 6110.63,4097.41 h50
  text "GND" at 5695.84,4035.33 h50
  text "GND" at 6186.49,4035.33 h50
  text "M4x4" at 7509.29,3673.26 h60
  text "SCREWS" at 7509.29,3621.85 h40
Top Solder Mask Layer:
  drawing of 170 lines, arcs and shapes, not listed
Bottom Solder Mask Layer:
  region: 6849.51,4403.35 6989.51,4403.35 6989.51,4263.35 6849.51,4263.35
  region: 6849.51,4108.07 6989.51,4108.07 6989.51,3968.07 6849.51,3968.07
  region: 6849.51,3812.8 6989.51,3812.8 6989.51,3672.8 6849.51,3672.8
  region: 4802.38,3812.76 4942.38,3812.76 4942.38,3672.76 4802.38,3672.76
  region: 4802.26,4108.07 4942.26,4108.07 4942.26,3968.07 4802.26,3968.07
  region: 4802.26,4403.28 4942.26,4403.28 4942.26,4263.28 4802.26,4263.28
  region: 4967.92,4240.36 5018.18,4240.36 5018.18,4172.89 4967.92,4172.89
  region: 4785.65,4215.9 5018.18,4215.9 5018.18,4172.89 4785.65,4172.89
  region: 4728.39,4372.03 4774.94,4372.03 4774.94,3649.4 4728.39,3649.4
  region: 4726.42,3920.54 4908.88,3920.54 4908.88,3877.63 4726.42,3877.63
  region: 4785.65,3625.4 5018.18,3625.4 5018.18,3582.39 4785.65,3582.39
  region: 6773.66,4255.13 6824.05,4255.13 6824.05,4172.91 6773.66,4172.91
  region: 6773.66,4215.82 6956.12,4215.82 6956.12,4172.91 6773.66,4172.91
  region: 6832.89,3920.65 7065.42,3920.65 7065.42,3877.64 6832.89,3877.64
  region: 7017.02,4372.03 7063.58,4372.03 7063.58,3649.4 7017.02,3649.4
  region: 6773.66,3664.58 6824.05,3664.58 6824.05,3582.36 6773.66,3582.36
  region: 6773.66,3625.26 6956.12,3625.26 6956.12,3582.36 6773.66,3582.36
  region: 4802.38,4439.03 5313.4,4439.03 5313.4,4396.12 4802.38,4396.12
  region: 4802.38,4143.73 5313.4,4143.73 5313.4,4100.82 4802.38,4100.82
  region: 4802.38,3848.53 5313.4,3848.53 5313.4,3805.62 4802.38,3805.62
  region: 6989.48,3805.62 6528.76,3805.62 6528.76,3848.53 6989.48,3848.53
  region: 6989.48,4396.12 6528.76,4396.12 6528.76,4439.03 6989.48,4439.03
  region: 6989.48,4100.82 6528.76,4100.82 6528.76,4143.73 6989.48,4143.73
  region: 5156.79,3913.3 5156.79,4053.3 5226.79,4053.3 5226.79,3913.3
  region: 5156.79,4208.6 5156.79,4348.6 5226.79,4348.6 5226.79,4208.6
  region: 5156.79,3618.1 5156.79,3758.1 5226.79,3758.1 5226.79,3618.1
  region: 4967.92,3649.86 5018.18,3649.86 5018.18,3582.39 4967.92,3582.39
  region: 6635.37,3758.1 6635.37,3618.1 6565.37,3618.1 6565.37,3758.1
  region: 6635.37,4053.3 6635.37,3913.3 6565.37,3913.3 6565.37,4053.3
  region: 6635.37,4348.6 6635.37,4208.6 6565.37,4208.6 6565.37,4348.6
